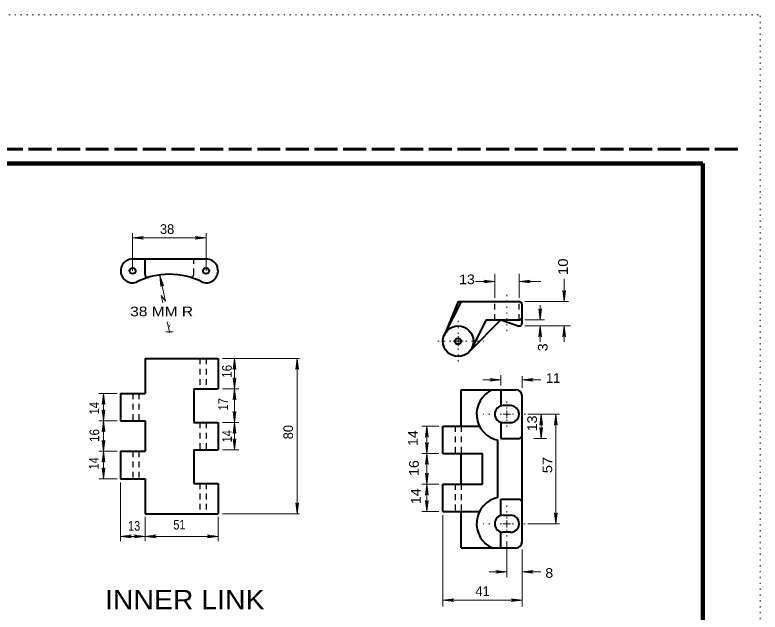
# Model space of a CAD drawing. Extents: x 312583 to 312854, y 144419 to 144597.
# Drawn here: x 312794.9 to 312853.5, y 144549.8 to 144596.8 of the extents above; entities that cross this region are included whole.
import ezdxf
from ezdxf.enums import TextEntityAlignment as Align

# ---------------------------------------------------------------- set-up
doc = ezdxf.new("R2010")
doc.units = 0
doc.header["$LTSCALE"] = 0.3
for name, pattern in [('DOTTED', [1.5, 0.3, -1.2]), ('LONG_DASHED', [7.5, 6, -1.5]), ('SHORT_DASHED', [2.7, 1.5, -1.2])]:
    doc.linetypes.add(name, pattern=pattern)
for name, color, linetype, lineweight in [('1', 7, 'Continuous', 40), ('2', 7, 'Continuous', 13), ('62', 7, 'DOTTED', 13), ('63', 7, 'LONG_DASHED', 60)]:
    doc.layers.add(name, color=color, linetype=linetype, lineweight=lineweight)

msp = doc.modelspace()

# ---------------------------------------------------------------- linework, layer by layer
at = {"layer": '1', "lineweight": 158}
msp.add_line((312849, 144423.1446), (312849, 144585.0846), dxfattribs=at)
at = {"layer": '1'}
for p, q in [((312804.1439, 144577.5705), (312809.9093, 144577.5705)), ((312805.1099, 144576.3668), (312805.1099, 144577.5705)), ((312829.7486, 144574.2123), (312828.637, 144571.5596)), ((312829.9863, 144574.2123), (312828.6753, 144571.6439)), ((312829.7486, 144574.2123), (312834.5403, 144574.2123)), ((312834.778, 144572.5333), (312834.778, 144573.9746)), ((312833.099, 144572.7709), (312830.5996, 144570.2486)), ((312831.949, 144572.7709), (312830.8143, 144570.5553)), ((312831.949, 144572.7709), (312834.5403, 144572.7709)), ((312833.099, 144572.7709), (312834.4636, 144572.3033)), ((312805.1099, 144569.7352), (312810.8599, 144569.7352)), ((312805.1099, 144569.7352), (312805.1099, 144566.9752)), ((312810.8599, 144569.7352), (312810.8599, 144567.3355)), ((312803.1933, 144566.9752), (312805.1099, 144566.9752)), ((312803.1933, 144566.9752), (312803.1933, 144564.8208)), ((312808.9433, 144567.3355), (312810.8599, 144567.3355)), ((312808.9433, 144567.3355), (312808.9433, 144564.7058)), ((312829.9863, 144567.2778), (312834.295, 144567.2778)), ((312829.9863, 144564.4028), (312829.9863, 144567.2778)), ((312833.099, 144567.2778), (312833.099, 144566.0052)), ((312834.778, 144555.2948), (312834.778, 144566.7948)), ((312833.8656, 144566.0282), (312833.2906, 144566.0282)), ((312803.1933, 144564.8208), (312805.1099, 144564.8208)), ((312805.1099, 144564.8208), (312805.1099, 144562.4288)), ((312808.9433, 144564.7058), (312810.8599, 144564.7058)), ((312810.8599, 144564.7058), (312810.8599, 144562.5515)), ((312833.099, 144564.7172), (312833.099, 144563.4445)), ((312833.2906, 144564.6865), (312833.8656, 144564.6865)), ((312828.545, 144562.2485), (312828.545, 144564.4028)), ((312828.545, 144564.4028), (312831.4276, 144564.4028)), ((312833.099, 144563.4445), (312834.5403, 144563.4445)), ((312832.8613, 144558.7832), (312832.8613, 144563.3065)), ((312803.1933, 144562.4288), (312805.1099, 144562.4288)), ((312803.1933, 144562.4288), (312803.1933, 144560.2745)), ((312808.9433, 144562.5515), (312810.8599, 144562.5515)), ((312808.9433, 144562.5515), (312808.9433, 144559.9065)), ((312828.545, 144562.2485), (312831.6653, 144562.2485)), ((312829.9863, 144559.8488), (312829.9863, 144562.2485)), ((312831.6653, 144559.8488), (312831.6653, 144562.2485)), ((312803.1933, 144560.2745), (312805.1099, 144560.2745)), ((312805.1099, 144560.2745), (312805.1099, 144557.5145)), ((312808.9433, 144559.9065), (312810.8599, 144559.9065)), ((312810.8599, 144559.9065), (312810.8599, 144557.5145)), ((312828.545, 144559.8488), (312831.6653, 144559.8488)), ((312828.545, 144557.6945), (312828.545, 144559.8488)), ((312833.099, 144558.6528), (312834.5403, 144558.6528)), ((312833.099, 144557.3802), (312833.099, 144558.6528)), ((312828.545, 144557.6945), (312831.4276, 144557.6945)), ((312829.9863, 144554.8195), (312829.9863, 144557.6945)), ((312805.1099, 144557.5145), (312810.8599, 144557.5145)), ((312833.2906, 144557.4032), (312833.8656, 144557.4032)), ((312833.099, 144554.8195), (312833.099, 144556.0922)), ((312833.8656, 144556.0615), (312833.2906, 144556.0615)), ((312829.9863, 144554.8195), (312834.295, 144554.8195))]:
    msp.add_line(p, q, dxfattribs=at)
at = {"layer": '1', "linetype": 'SHORT_DASHED', "lineweight": 25}
for p, q in [((312808.9433, 144576.3668), (312808.9433, 144577.5705)), ((312832.6236, 144572.7709), (312832.6236, 144574.2123)), ((312834.5403, 144572.7709), (312834.5403, 144574.2123)), ((312809.4263, 144569.7352), (312809.4263, 144567.3355)), ((312809.9093, 144569.7352), (312809.9093, 144567.3355)), ((312804.1516, 144566.9752), (312804.1516, 144564.8208)), ((312804.6346, 144566.9752), (312804.6346, 144564.8208)), ((312809.4263, 144564.6982), (312809.4263, 144562.5438)), ((312809.9093, 144564.6982), (312809.9093, 144562.5438)), ((312829.5033, 144564.4028), (312829.5033, 144562.2485)), ((312829.9863, 144564.4028), (312829.9863, 144562.2485)), ((312804.1516, 144562.4288), (312804.1516, 144560.2745)), ((312804.6346, 144562.4288), (312804.6346, 144560.2745)), ((312809.4263, 144559.9065), (312809.4263, 144557.5145)), ((312809.9093, 144559.9065), (312809.9093, 144557.5145)), ((312829.5033, 144559.8565), (312829.5033, 144557.7022)), ((312829.9863, 144559.8565), (312829.9863, 144557.7022))]:
    msp.add_line(p, q, dxfattribs=at)
at = {"layer": '1', "linetype": 'DOTTED', "lineweight": 13}
for p, q in [((312833.582, 144571.8893), (312833.582, 144574.7413)), ((312807.0266, 144572.3188), (312807.0266, 144571.5522))]:
    msp.add_line(p, q, dxfattribs=at)
at = {"layer": '1', "lineweight": 158}
msp.add_lwpolyline([(312616.5, 144423.1446), (312616.5, 144585.0846), (312849, 144585.0846)], dxfattribs=at)
at = {"layer": '1'}
for centre, radius in [((312804.1305, 144576.6352), 0.2396), ((312809.9189, 144576.6352), 0.2396), ((312829.7448, 144571.0958), 1.1998), ((312829.7448, 144571.0958), 0.2415)]:
    msp.add_circle(centre, radius, dxfattribs=at)
for centre, radius, start, end in [((312804.1325, 144576.6349), 0.9355, 89.30098, 288.88136), ((312809.9207, 144576.6349), 0.9355, 251.11864, 90.69902), ((312807.0266, 144570.6168), 5.75, 63.21287, 116.78713), ((312805.3495, 144576.3668), 0.2396, 180, 286.26021), ((312834.5345, 144573.9689), 0.2396, 0, 90), ((312834.5345, 144573.0105), 0.2396, 270, 0), ((312834.5345, 144572.5314), 0.2396, 251.56505, 0.45836), ((312833.2906, 144565.3573), 2.0966, 113.91014, 258.17613), ((312834.295, 144566.7948), 0.4792, 0, 90), ((312833.2906, 144565.3573), 0.6708, 90, 270), ((312833.8656, 144565.3573), 0.6708, 270, 90), ((312834.5345, 144563.6803), 0.2396, 270, 0), ((312833.2906, 144556.7323), 2.0966, 101.82388, 246.08986), ((312834.5345, 144558.4094), 0.2396, 0, 90), ((312833.2906, 144556.7323), 0.6708, 90, 270), ((312833.8656, 144556.7323), 0.6708, 270, 90), ((312834.295, 144555.2948), 0.4792, 270, 0)]:
    msp.add_arc(centre, radius, start, end, dxfattribs=at)
at = {"layer": '1', "linetype": 'SHORT_DASHED', "lineweight": 25}
msp.add_arc((312808.7037, 144576.3668), 0.2396, 253.73979, 0, dxfattribs=at)
at = {"layer": '2'}
for p, q in [((312804.1363, 144576.6352), (312804.1363, 144579.6022)), ((312804.1363, 144579.2342), (312805.0026, 144579.3415)), ((312805.0026, 144579.3415), (312804.7266, 144579.2342)), ((312809.0583, 144579.3415), (312809.3343, 144579.2342)), ((312809.9246, 144579.2342), (312809.0583, 144579.3415)), ((312809.9246, 144576.6352), (312809.9246, 144579.6022)), ((312804.1363, 144579.2342), (312809.9246, 144579.2342)), ((312804.1363, 144579.2342), (312805.0026, 144579.1268)), ((312805.0026, 144579.1268), (312804.7266, 144579.2342)), ((312809.0583, 144579.1268), (312809.3343, 144579.2342)), ((312809.9246, 144579.2342), (312809.0583, 144579.1268)), ((312832.6236, 144574.5036), (312832.6236, 144576.3896)), ((312834.5403, 144574.5036), (312834.5403, 144576.3896)), ((312806.2676, 144576.2672), (312806.3519, 144575.4008)), ((312806.2676, 144576.2672), (312806.5589, 144575.4468)), ((312831.1056, 144575.7993), (312832.6236, 144575.7993)), ((312831.7573, 144575.9066), (312832.0333, 144575.7993)), ((312832.6236, 144575.7993), (312831.7573, 144575.9066)), ((312831.7573, 144575.6919), (312832.0333, 144575.7993)), ((312832.6236, 144575.7993), (312831.7573, 144575.6919)), ((312834.5403, 144575.7993), (312835.4066, 144575.9066)), ((312834.5403, 144575.7993), (312836.2576, 144575.7993)), ((312834.5403, 144575.7993), (312835.4066, 144575.6919)), ((312835.4066, 144575.9066), (312835.1306, 144575.7993)), ((312835.4066, 144575.6919), (312835.1306, 144575.7993)), ((312838.0823, 144574.2123), (312838.0823, 144576.0139)), ((312806.3519, 144575.4008), (312806.3979, 144575.6922)), ((312806.5589, 144575.4468), (312806.3979, 144575.6922)), ((312806.5053, 144574.1205), (312806.3749, 144574.6955)), ((312837.975, 144575.0786), (312838.0823, 144574.8026)), ((312838.0823, 144574.2123), (312837.975, 144575.0786)), ((312838.1896, 144575.0786), (312838.0823, 144574.8026)), ((312838.0823, 144574.2123), (312838.1896, 144575.0786)), ((312834.9926, 144574.2123), (312838.435, 144574.2123)), ((312836.089, 144573.6373), (312836.1963, 144573.3613)), ((312836.1963, 144572.7709), (312836.089, 144573.6373)), ((312836.1963, 144572.7709), (312836.1963, 144573.9439)), ((312836.3036, 144573.6373), (312836.1963, 144573.3613)), ((312836.1963, 144572.7709), (312836.3036, 144573.6373)), ((312807.0266, 144571.8435), (312806.8503, 144572.6178)), ((312834.9926, 144572.7709), (312836.549, 144572.7709)), ((312834.9926, 144572.3033), (312838.573, 144572.3033)), ((312836.1963, 144572.3033), (312836.089, 144571.4369)), ((312836.1963, 144571.0536), (312836.1963, 144572.3033)), ((312836.1963, 144572.3033), (312836.3036, 144571.4369)), ((312838.0823, 144572.3033), (312837.975, 144571.4369)), ((312838.0823, 144571.0536), (312838.0823, 144572.3033)), ((312838.0823, 144572.3033), (312838.1896, 144571.4369)), ((312806.7429, 144571.8435), (312807.3256, 144571.8435)), ((312836.089, 144571.4369), (312836.1963, 144571.7129)), ((312836.3036, 144571.4369), (312836.1963, 144571.7129)), ((312837.975, 144571.4369), (312838.0823, 144571.7129)), ((312838.1896, 144571.4369), (312838.0823, 144571.7129)), ((312829.7486, 144571.0996), (312829.3653, 144571.0996)), ((312829.7486, 144571.0996), (312829.7486, 144571.4829)), ((312829.7486, 144571.0996), (312830.132, 144571.0996)), ((312829.7486, 144571.0996), (312829.7486, 144570.7163)), ((312811.2126, 144569.7352), (312817.2616, 144569.7352)), ((312812.1403, 144569.7352), (312812.0329, 144568.8688)), ((312812.1403, 144569.7352), (312812.2476, 144568.8688)), ((312817.0776, 144569.7352), (312816.9703, 144568.8688)), ((312817.0776, 144557.5145), (312817.0776, 144569.7352)), ((312817.0776, 144569.7352), (312817.1849, 144568.8688)), ((312812.0329, 144568.8688), (312812.1403, 144569.1448)), ((312812.2476, 144568.8688), (312812.1403, 144569.1448)), ((312816.9703, 144568.8688), (312817.0776, 144569.1448)), ((312817.1849, 144568.8688), (312817.0776, 144569.1448)), ((312812.0329, 144568.2018), (312812.1403, 144567.9258)), ((312812.1403, 144567.3355), (312812.0329, 144568.2018)), ((312812.2476, 144568.2018), (312812.1403, 144567.9258)), ((312812.1403, 144567.3355), (312812.2476, 144568.2018)), ((312832.2326, 144568.1672), (312832.5086, 144568.0598)), ((312833.099, 144568.0598), (312832.2326, 144568.1672)), ((312833.099, 144567.6152), (312833.099, 144568.4355)), ((312834.778, 144567.4388), (312834.778, 144568.3512)), ((312834.778, 144568.0598), (312835.6443, 144568.1672)), ((312835.6443, 144568.1672), (312835.3683, 144568.0598)), ((312831.6883, 144568.0598), (312833.099, 144568.0598)), ((312832.2326, 144567.9525), (312832.5086, 144568.0598)), ((312833.099, 144568.0598), (312832.2326, 144567.9525)), ((312834.778, 144568.0598), (312836.2576, 144568.0598)), ((312834.778, 144568.0598), (312835.6443, 144567.9525)), ((312835.6443, 144567.9525), (312835.3683, 144568.0598)), ((312802.9096, 144566.9752), (312801.4836, 144566.9752)), ((312801.8516, 144566.9752), (312801.7443, 144566.1088)), ((312801.8516, 144566.9752), (312801.9589, 144566.1088)), ((312811.2126, 144567.3355), (312812.5006, 144567.3355)), ((312812.1403, 144567.3355), (312812.0329, 144566.4692)), ((312812.1403, 144567.3355), (312812.2476, 144566.4692)), ((312801.7443, 144566.1088), (312801.8516, 144566.3848)), ((312801.9589, 144566.1088), (312801.8516, 144566.3848)), ((312812.0329, 144566.4692), (312812.1403, 144566.7452)), ((312812.2476, 144566.4692), (312812.1403, 144566.7452)), ((312801.7443, 144565.6872), (312801.8516, 144565.4112)), ((312801.8516, 144564.8208), (312801.7443, 144565.6872)), ((312801.9589, 144565.6872), (312801.8516, 144565.4112)), ((312801.8516, 144564.8208), (312801.9589, 144565.6872)), ((312812.0329, 144565.5722), (312812.1403, 144565.2962)), ((312812.1403, 144564.7058), (312812.0329, 144565.5722)), ((312812.2476, 144565.5722), (312812.1403, 144565.2962)), ((312812.1403, 144564.7058), (312812.2476, 144565.5722)), ((312833.582, 144565.3612), (312833.2906, 144565.3612)), ((312833.582, 144565.3612), (312833.582, 144565.6448)), ((312833.582, 144565.3612), (312833.8656, 144565.3612)), ((312833.582, 144565.3612), (312833.582, 144565.0698)), ((312835.215, 144565.3612), (312837.7296, 144565.3612)), ((312836.2737, 144565.3612), (312836.1663, 144564.4948)), ((312836.2737, 144563.4445), (312836.2737, 144565.3612)), ((312836.2737, 144565.3612), (312836.381, 144564.4948)), ((312837.4383, 144565.3612), (312837.331, 144564.4948)), ((312837.4383, 144556.7208), (312837.4383, 144565.3612)), ((312837.4383, 144565.3612), (312837.5456, 144564.4948)), ((312802.9096, 144564.8208), (312801.4836, 144564.8208)), ((312801.8516, 144564.8208), (312801.7443, 144563.9545)), ((312801.8516, 144564.8208), (312801.9589, 144563.9545)), ((312811.2126, 144564.7058), (312812.5006, 144564.7058)), ((312812.1403, 144564.7058), (312812.0329, 144563.8395)), ((312812.1403, 144564.7058), (312812.2476, 144563.8395)), ((312836.1663, 144564.4948), (312836.2737, 144564.7708)), ((312836.381, 144564.4948), (312836.2737, 144564.7708)), ((312837.331, 144564.4948), (312837.4383, 144564.7708)), ((312837.5456, 144564.4948), (312837.4383, 144564.7708)), ((312801.7443, 144563.9545), (312801.8516, 144564.2305)), ((312801.9589, 144563.9545), (312801.8516, 144564.2305)), ((312812.0329, 144563.8395), (312812.1403, 144564.1155)), ((312812.2476, 144563.8395), (312812.1403, 144564.1155)), ((312828.2153, 144564.4028), (312826.889, 144564.4028)), ((312827.2723, 144564.4028), (312827.165, 144563.5365)), ((312827.2723, 144564.4028), (312827.3796, 144563.5365)), ((312836.1663, 144564.3108), (312836.2737, 144564.0348)), ((312836.2737, 144563.4445), (312836.1663, 144564.3108)), ((312836.381, 144564.3108), (312836.2737, 144564.0348)), ((312836.2737, 144563.4445), (312836.381, 144564.3108)), ((312827.165, 144563.5365), (312827.2723, 144563.8125)), ((312827.3796, 144563.5365), (312827.2723, 144563.8125)), ((312835.7095, 144563.4445), (312836.7193, 144563.4445)), ((312801.7443, 144563.2952), (312801.8516, 144563.0192)), ((312801.8516, 144562.4288), (312801.7443, 144563.2952)), ((312801.9589, 144563.2952), (312801.8516, 144563.0192)), ((312801.8516, 144562.4288), (312801.9589, 144563.2952)), ((312812.0329, 144563.4178), (312812.1403, 144563.1418)), ((312812.1403, 144562.5515), (312812.0329, 144563.4178)), ((312812.2476, 144563.4178), (312812.1403, 144563.1418)), ((312812.1403, 144562.5515), (312812.2476, 144563.4178)), ((312827.165, 144563.1148), (312827.2723, 144562.8388)), ((312827.2723, 144562.2485), (312827.165, 144563.1148)), ((312827.3796, 144563.1148), (312827.2723, 144562.8388)), ((312827.2723, 144562.2485), (312827.3796, 144563.1148)), ((312802.9096, 144562.4288), (312801.4836, 144562.4288)), ((312801.8516, 144562.4288), (312801.7443, 144561.5625)), ((312801.8516, 144562.4288), (312801.9589, 144561.5625)), ((312811.2126, 144562.5515), (312812.5006, 144562.5515)), ((312801.7443, 144561.5625), (312801.8516, 144561.8385)), ((312801.9589, 144561.5625), (312801.8516, 144561.8385)), ((312828.2153, 144562.2485), (312826.889, 144562.2485)), ((312827.2723, 144562.2485), (312827.165, 144561.3822)), ((312827.2723, 144562.2485), (312827.3796, 144561.3822)), ((312801.7443, 144561.1408), (312801.8516, 144560.8648)), ((312801.8516, 144560.2745), (312801.7443, 144561.1408)), ((312801.9589, 144561.1408), (312801.8516, 144560.8648)), ((312801.8516, 144560.2745), (312801.9589, 144561.1408)), ((312827.165, 144561.3822), (312827.2723, 144561.6582)), ((312827.3796, 144561.3822), (312827.2723, 144561.6582)), ((312827.165, 144560.7152), (312827.2723, 144560.4392)), ((312827.2723, 144559.8488), (312827.165, 144560.7152)), ((312827.3796, 144560.7152), (312827.2723, 144560.4392)), ((312827.2723, 144559.8488), (312827.3796, 144560.7152)), ((312802.9096, 144560.2745), (312801.4836, 144560.2745)), ((312803.1933, 144559.9755), (312803.1933, 144555.3525)), ((312828.2153, 144559.8488), (312826.889, 144559.8488)), ((312827.2723, 144559.8488), (312827.165, 144558.9825)), ((312827.2723, 144559.8488), (312827.3796, 144558.9825)), ((312827.165, 144558.9825), (312827.2723, 144559.2585)), ((312827.3796, 144558.9825), (312827.2723, 144559.2585)), ((312816.9703, 144558.3808), (312817.0776, 144558.1048)), ((312817.0776, 144557.5145), (312816.9703, 144558.3808)), ((312817.1849, 144558.3808), (312817.0776, 144558.1048)), ((312817.0776, 144557.5145), (312817.1849, 144558.3808)), ((312827.165, 144558.5608), (312827.2723, 144558.2848)), ((312827.2723, 144557.6945), (312827.165, 144558.5608)), ((312827.3796, 144558.5608), (312827.2723, 144558.2848)), ((312827.2723, 144557.6945), (312827.3796, 144558.5608)), ((312828.2153, 144557.6945), (312826.889, 144557.6945)), ((312837.331, 144557.5872), (312837.4383, 144557.3112)), ((312837.4383, 144556.7208), (312837.331, 144557.5872)), ((312837.5456, 144557.5872), (312837.4383, 144557.3112)), ((312837.4383, 144556.7208), (312837.5456, 144557.5872)), ((312805.1099, 144557.2692), (312805.1099, 144555.3525)), ((312810.8599, 144557.2692), (312810.8599, 144555.3525)), ((312811.2126, 144557.5145), (312817.2616, 144557.5145)), ((312828.545, 144557.3955), (312828.545, 144550.2118)), ((312833.582, 144556.7208), (312833.582, 144557.0045)), ((312833.582, 144556.7208), (312833.2983, 144556.7208)), ((312833.582, 144556.7208), (312833.8733, 144556.7208)), ((312833.582, 144556.7208), (312833.582, 144556.4295)), ((312835.215, 144556.7208), (312837.7296, 144556.7208)), ((312803.1933, 144555.7358), (312804.0596, 144555.8432)), ((312804.0596, 144555.8432), (312803.7836, 144555.7358)), ((312804.2436, 144555.8432), (312804.5196, 144555.7358)), ((312805.1099, 144555.7358), (312804.2436, 144555.8432)), ((312805.1099, 144555.7358), (312805.9763, 144555.8432)), ((312805.9763, 144555.8432), (312805.7003, 144555.7358)), ((312809.9936, 144555.8432), (312810.2696, 144555.7358)), ((312810.8599, 144555.7358), (312809.9936, 144555.8432)), ((312803.1933, 144555.7358), (312804.0596, 144555.6285)), ((312804.0596, 144555.6285), (312803.7836, 144555.7358)), ((312804.2436, 144555.6285), (312804.5196, 144555.7358)), ((312805.1099, 144555.7358), (312804.2436, 144555.6285)), ((312805.1099, 144555.7358), (312805.9763, 144555.6285)), ((312805.9763, 144555.6285), (312805.7003, 144555.7358)), ((312809.9936, 144555.6285), (312810.2696, 144555.7358)), ((312810.8599, 144555.7358), (312809.9936, 144555.6285)), ((312833.582, 144555.3102), (312833.582, 144552.5348)), ((312834.778, 144554.7122), (312834.778, 144550.2118)), ((312832.1943, 144552.9488), (312833.582, 144552.9488)), ((312832.7156, 144553.0562), (312832.9916, 144552.9488)), ((312833.582, 144552.9488), (312832.7156, 144553.0562)), ((312832.7156, 144552.8415), (312832.9916, 144552.9488)), ((312833.582, 144552.9488), (312832.7156, 144552.8415)), ((312834.778, 144552.9488), (312835.6443, 144553.0562)), ((312834.778, 144552.9488), (312836.2576, 144552.9488)), ((312834.778, 144552.9488), (312835.6443, 144552.8415)), ((312835.6443, 144553.0562), (312835.3683, 144552.9488)), ((312835.6443, 144552.8415), (312835.3683, 144552.9488)), ((312828.545, 144550.7102), (312829.4113, 144550.8175)), ((312828.545, 144550.7102), (312834.778, 144550.7102)), ((312828.545, 144550.7102), (312829.4113, 144550.6028)), ((312829.4113, 144550.8175), (312829.1353, 144550.7102)), ((312829.4113, 144550.6028), (312829.1353, 144550.7102)), ((312833.9116, 144550.8175), (312834.1876, 144550.7102)), ((312834.778, 144550.7102), (312833.9116, 144550.8175)), ((312833.9116, 144550.6028), (312834.1876, 144550.7102)), ((312834.778, 144550.7102), (312833.9116, 144550.6028))]:
    msp.add_line(p, q, dxfattribs=at)
at = {"layer": '2', "linetype": 'DOTTED'}
for p, q in [((312829.7486, 144571.6746), (312829.7486, 144572.7403)), ((312829.1736, 144571.0996), (312828.0543, 144571.0996)), ((312830.3236, 144571.0996), (312831.7496, 144571.0996)), ((312829.7486, 144570.5246), (312829.7486, 144569.4819)), ((312833.582, 144565.7905), (312833.582, 144566.6645)), ((312833.145, 144565.3612), (312831.7113, 144565.3612)), ((312834.0113, 144565.3612), (312835.215, 144565.3612)), ((312833.582, 144564.9242), (312833.582, 144564.0732)), ((312833.582, 144557.1502), (312833.582, 144558.2082)), ((312833.1526, 144556.7208), (312831.7113, 144556.7208)), ((312834.0036, 144556.7208), (312835.215, 144556.7208)), ((312833.582, 144556.2838), (312833.582, 144555.3102))]:
    msp.add_line(p, q, dxfattribs=at)
at = {"layer": '2'}
for points in [[(312806.3749, 144574.6955), (312806.7276, 144574.2432), (312806.2676, 144576.2672)], [(312812.1403, 144562.5515), (312812.1403, 144564.7058), (312812.1403, 144567.3355), (312812.1403, 144569.7352)], [(312801.8516, 144560.2745), (312801.8516, 144562.4288), (312801.8516, 144564.8208), (312801.8516, 144566.9752)], [(312827.2723, 144557.6945), (312827.2723, 144559.8488), (312827.2723, 144562.2485), (312827.2723, 144564.4028)], [(312803.1933, 144555.7358), (312805.1099, 144555.7358), (312810.8599, 144555.7358)]]:
    msp.add_lwpolyline(points, dxfattribs=at)
at = {"layer": '62'}
msp.add_line((312601.2, 144596.7846), (312853.5, 144596.7846), dxfattribs=at)
msp.add_lwpolyline([(312601.2, 144418.5846), (312853.5, 144418.5846), (312853.5, 144596.7846)], dxfattribs=at)
at = {"layer": '63'}
msp.add_line((312851.75, 144586.2246), (312583.526, 144586.2246), dxfattribs=at)

# ---------------------------------------------------------------- texts
at = {"layer": '2'}
for s, p in [('38', (312806.2822, 144579.5438)), ('11 ', (312836.6563, 144567.8173)), ('41 ', (312831.1016, 144551.0399))]:
    msp.add_text(s, height=0.76, dxfattribs=at).set_placement(p)
for s, width, p in [('10 ', 1.15, (312838.375, 144576.3076)), ('3 ', 1.1, (312836.7832, 144570.3071)), ('16', 0.9, (312811.9384, 144568.2159)), ('17', 0.85, (312811.6471, 144565.6483)), ('14', 0.85, (312801.4993, 144565.3462)), ('13 ', 1.1, (312835.9422, 144564.0057)), ('16', 0.9, (312801.507, 144563.1659)), ('14', 0.85, (312811.9434, 144563.1328)), ('14 ', 1.1, (312826.566, 144562.8461)), ('14', 0.85, (312801.4646, 144560.998)), ('16 ', 1.1, (312826.6468, 144560.4878)), ('57 ', 1.15, (312837.1418, 144560.7002)), ('14 ', 1.1, (312826.7951, 144558.2713))]:
    msp.add_text(s, height=0.76, rotation=90, dxfattribs=dict(at, width=width)).set_placement(p)
for s, width, p in [('13 ', 1.1, (312829.8152, 144575.5855)), ('38 MM R', 1.2, (312803.9446, 144573.0615)), ('51', 0.85, (312807.3363, 144556.2755)), ('13', 0.85, (312803.7735, 144556.1891)), ('8 ', 1.1, (312836.6016, 144552.4725))]:
    msp.add_text(s, height=0.76, dxfattribs=dict(at, width=width)).set_placement(p)
msp.add_text('80', height=0.76, rotation=90, dxfattribs=at).set_placement((312816.7562, 144563.3723))
at = {"layer": '2', "width": 1.1}
msp.add_text('INNER LINK', height=1.52, dxfattribs=at).set_placement((312808.2344, 144549.9955), align=Align.CENTER)

doc.saveas('drawing.dxf')
